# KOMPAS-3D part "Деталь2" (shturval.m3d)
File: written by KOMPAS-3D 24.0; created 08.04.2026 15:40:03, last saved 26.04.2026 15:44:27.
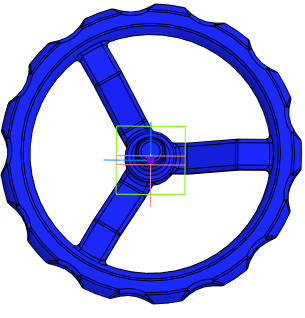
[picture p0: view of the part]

Document properties: Автор: R2D2; Полное имя файла: C:\Работа\VSO2130M-F-S Клапан запорный DN.ru\DN80\DN80\shturval.m3d

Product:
- Body: Твердое тело1  | qty 1
    Масса: 2.292394
- Part/product: Деталь2
    Масса: 2.292394
    additional columns: Типовые

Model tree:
1. Твердое тело1  (labels: Твердое тело1)
2. Масштабирование:1
3. Масштабирование : Твердое тело1
     Масштаб по оси Х = 1; Масштаб по оси Y = 1; Масштаб по оси Z = 1; Коэффициент = 1.49

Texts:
  Масштабирование : Вершина.Начало координат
